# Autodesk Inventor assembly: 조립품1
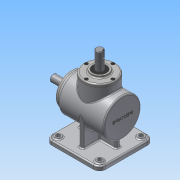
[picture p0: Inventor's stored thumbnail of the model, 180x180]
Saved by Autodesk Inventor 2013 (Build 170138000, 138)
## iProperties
Created: 2015-07
Part Number: 조립품1
Document SubType Name: Assembly
Designer: ST3
Author: ST3
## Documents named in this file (14)
- C:\Users\ST3\Desktop\450705V1010\조립품1.iam
- C:\Users\ST3\Desktop\450705V1010\본체.ipt
- C:\Users\ST3\Desktop\450705V1010\M4.ipt
- C:\Users\ST3\Desktop\450705V1010\메인 베벨기어.ipt
- C:\Users\ST3\Desktop\450705V1010\메인 축.ipt
- 메인 축.ipt
- C:\Users\ST3\Desktop\450705V1010\베어링 6203.ipt
- C:\Users\ST3\Desktop\450705V1010\서브 베벨기어.ipt
- C:\Users\ST3\Desktop\450705V1010\서브 축.ipt
- 서브 축.ipt
- C:\Users\ST3\Desktop\450705V1010\오일실.ipt
- C:\Users\ST3\Desktop\450705V1010\커버.ipt
- C:\Users\ST3\Desktop\450705V1010\키 4x4.ipt
- C:\Users\ST3\Desktop\450705V1010\키 5x5.ipt
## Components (8 placed, 1 different names)
1. M4:1
2. M4:2
3. M4:3
4. M4:4
5. M4:5
6. M4:6
7. M4:7
8. M4:8
